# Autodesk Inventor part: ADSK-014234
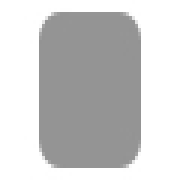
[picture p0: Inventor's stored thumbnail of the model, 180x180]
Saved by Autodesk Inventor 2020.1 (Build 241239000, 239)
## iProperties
Created: 2019-01
Part Number: ADSK-014234
Material: Stahl, weich
Document SubType Name: Modeling
Designer: lutzd
Language: de-DE
Size Designation: 5 x 39,384472 x 39,384472
Categories: <MemberInstance><Categories><Category DisplayName="Sonstige Bauteile" InternalName="5aa15e00-363f-49f2-933f-16f664388e3f" Mnemonic="OTHER"><Category DisplayName
Mass: 60.0398 g
Surface Area: 38.0412 cm^2
Volume: 7.64838 cm^3
Density: 7.85 g/cm^3
Appearance: Halbpoliert
IsCustomPart: 1
Title: Endcap
Author: lutzd
Revision Number: -
Dimensions: 39,4x39,4x5 mm
Mass: 0,06 kg
DocNumber: ADSK-014234
Folder: 01 - Themengebiete\Simplification\01 - Packaging machine\ADSK-014200\Frame\
VDS_Category: 3D Komponenten
VDS_NumSchm: Autodesk
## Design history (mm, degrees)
sketch "Sketch1"
  geometry: L1 (0, 20.175)-(0, -21.446); L2 (-20.203, 0)-(20.169, 0); L3 (-19.692, 19.692)-(19.692, 19.692); L4 (19.692, 19.692)-(19.692, -19.692); L5 (19.692, -19.692)-(-19.692, -19.692); L6 (-19.692, -19.692)-(-19.692, 19.692); 1 further point
  constraints: 12 end point, 2 horizontal, 2 parallel, 2 point on line, 1 perpendicular, 1 vertical
  dimensions: "d0" = 39.38447 distance between parallel lines of L5 L3 (= height); "d1" = 19.69224 distance between parallel lines of L2 L3 (= 0.5 x height); "d2" = 39.38447 distance between parallel lines of L6 L4 (= width); "d3" = 19.69224 distance between parallel lines of L6 L1 (= 0.5 x width)
extrude "Extrusion1" new body sketch "Sketch1" distance "d4" = 5 (= thickness); taper "d5" = 0 deg
fillet "Fillet1" dims "d6" = 5 (= fillet), "d7" = 0, "fillet" = 5 [user parameter; used in 1 equation term]
chamfer "Chamfer1" distance "d8" = 0 (computed from chamfer); stored, may be unused: second distance "d9" = 2, angle "d10" = 45 deg; dims "d11" = 0, "chamfer" = 0 [user parameter; used in 1 equation term]
body "Solid1"
other parameters: "thickness" = 5 [user parameter; used in 1 equation term], "width" = 39.38447 [user parameter; used in 2 equation terms], "height" = 39.38447 [user parameter; used in 2 equation terms]
